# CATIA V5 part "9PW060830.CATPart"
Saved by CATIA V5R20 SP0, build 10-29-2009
Part number: 9PW060830
Revision: ANY
Definition: UNKNOWN
Nomenclature: 9PW060830
Source: Unknown
Bounding box of the stored display mesh (mm): x -174.5 to 0, y -11.046 to 3, z -4.1 to 4.1
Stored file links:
  C:\Users\Utente\Desktop\IO LAVORO\3D X SITO CF\CUMSA\3D files PW\pw060830\pw060830_ejection\9PW060830.CATPart
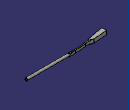
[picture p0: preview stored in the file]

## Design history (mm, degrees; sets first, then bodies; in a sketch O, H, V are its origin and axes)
Body1 "Chaflán2" (main body)
  Solid1: solid without history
